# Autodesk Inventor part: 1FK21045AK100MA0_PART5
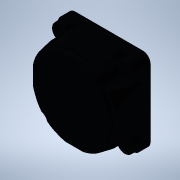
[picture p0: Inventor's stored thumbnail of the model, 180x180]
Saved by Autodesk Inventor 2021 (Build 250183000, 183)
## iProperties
Created: 2025-04
Part Number: 1FK21045AK100MA0_PART5
Material: Generic
Catalog Web Link: www.3dfindit.com
Description: -Servo synchronous motor
Document SubType Name: Modeling
Designer: psAdmin
Mass: 3.92604 g
Surface Area: 17.9521 cm^2
Volume: 3.92604 cm^3
Density: 1 g/cm^3
Appearance: PSOLRGB-48-56-69
Category: PARTsolutions
Title: 1FK21045AK100MA0_PART5
Author: Cadenas PARTsolutions
Comments: Servo synchronous motor
Sending System: PARTsolutions
Preprocessor: ST-DEVELOPER v19.3
PSOL_IDENT_0: {$CADENAS_DATA/23d-libs/siemens_ag/_cat_/e0/5f/1fk21045ak100ma0.prj},213 {VTYP=3D},{NB=1FK21045AK100
PSOL_IDENT_1: MA0_PART5},{LINA=1FK21045AK100MA0_PART5},{NN=1FK21045AK100MA0_PART5},{NOPRJ=TRUE},{DATE=19.08.2025 1
PSOL_IDENT_2: 4:01:03},{GEOMDATE=30.07.2025 02:01:57},{VERSION=},{LINEID=10},{WBVAR=},{WBNUMERIC=}  {NB=1FK21045AK
PSOL_IDENT_3: 100MA0_PART5},{LINA=1FK21045AK100MA0_PART5},{KT=DUMMY},{PREVIEW=../../../_pool_/0f/2c/p_d211_xx_0043
PSOL_IDENT_4: 8j.png},{DESCSHORT=SIMOTICS S-1FK2 HD, SINAMICS S210 3AC 400V-480V, 1.7 Nm, 6000 rpm},{DESCLONG=SIMO
PSOL_IDENT_5: TICS S-1FK2 HD servo motor M0=2.4 Nm; PN = 1.07 kW at nN=6000 rpm (380-480 V); PN = 0.75 kW at nN=30
PSOL_IDENT_6: 00 rpm (200-240 V); with holding brake; degree of protection IP64; cylindrical shaft D19x40mm; absol
PSOL_IDENT_7: ute encoder 22-bit + 12-bit multiturn (encoder AM22DQC); with OCC interface; plug size M17, rotatabl
PSOL_IDENT_8: e; SIMOTICS S-1FK2 servomotorfor a wide range of uses in industrial environments. SIMOTICS S‑1FK2 se
PSOL_IDENT_9: rvomotors are compact synchronous motors with a high dynamic performance that set themselves apart a
PSOL_IDENT_10: s a result of their high power density, degree of protection and overload capability. The motors are
PSOL_IDENT_11: available in two variants: as High Dynamic variant (highest dynamic performance as a result of the
PSOL_IDENT_12: low intrinsic moment of inertia for applications demanding a high dynamic performance with low moved
PSOL_IDENT_13: masses) - and as Compact variant (precise and stable closed-loop control for medium up to large mov
PSOL_IDENT_14: ed masses as a result of a medium intrinsic moment of inertia). SIMOTICSS‑1FK2 servomotors fully exp
PSOL_IDENT_15: loit their strengths in a system with the SINAMICSS210 frequency converter and simple connection usi
PSOL_IDENT_16: ng the one cable connection (OCC). Advantages include the short control and positioning times, fast
PSOL_IDENT_17: and precise correction of disturbing quantities as well as stable control with a high dynamic perfor
PSOL_IDENT_18: mance. The servo motors can be configured to address a wide range of requirements. For example with
PSOL_IDENT_19: and without holding brake, IP64 or IP65 degree of protection, singleturn or multiturn absolute encod
PSOL_IDENT_20: ers - to name just a few. Further, the servomotors are available in different shaft heights extendin
PSOL_IDENT_21: g from 20 to 100. A shaft sealing ring is available to achieve an IP65 degree of protection and for
PSOL_IDENT_22: subsequent mounting at the motor or as spare part. SIMOTICS - the optimum motor for each and every m
PSOL_IDENT_23: otion control application.},{INTNO=804766807114},{SUPPLIERALTNO=1FK2104-5AK10-0MA0},{MANUID=1FK21045
PSOL_IDENT_24: AK100MA0},{MANUNAME=Siemens},{MANUTYPEDESC=Synchronous motor 1FK2-HD 2,39 Nm},{AAU732=SIMOTICS},{AAO
PSOL_IDENT_25: 057=S-1FK2},{AAU734=SIMOTICS S-1FK2 HD servo motor M0=2.4 Nm; PN = 1.07 kW at nN=6000 rpm (380-480 V
PSOL_IDENT_26: ); PN = 0.75 kW at nN=3000 rpm (200-240 V); with holding brake; degree of protection IP64; cylindric
PSOL_IDENT_27: al shaft D19x40mm; absolute encoder 22-bit + 12-bit multiturn (encoder AM22DQC); with OCC interface;
PSOL_IDENT_28: plug size M17, rotatable;},{AAW338=Synchronous motor 1FK2-HD 2,39 Nm},{AAO742=SIMOTICS},{AAO663=404
PSOL_IDENT_29: 2948691236},{NOCUPEROU=1},{PRICEQUANTITY=1},{QUANTITYMIN=1},{QUANTITYINT=1},{CTN=85015100},{COO=DE},
PSOL_IDENT_30: {AAO676=1FK2104-5AK10-0MA0},{AAO677=Siemens AG},{ORDERUNIT=C62},{CONTENTUNIT=C62}
NB: 1FK21045AK100MA0_PART5
NT: Servo synchronous motor
NBSYN: $MANUID._PART5
LINA: 1FK21045AK100MA0_PART5
CATALOG: SIEMENS
PREVIEW: ../../../_pool_/0f/2c/p_d211_xx_00438j.png
DESCSHORT: SIMOTICS S-1FK2 HD, SINAMICS S210 3AC 400V-480V, 1.7 Nm, 6000 rpm
DESCLONG: SIMOTICS S-1FK2 HD servo motor M0=2.4 Nm; PN = 1.07 kW at nN=6000 rpm (380-480 V); PN = 0.75 kW at nN=3000 rpm (200-240 V); with holding brake; degree of protec
INTNO: 804766807114
SUPPLIERALTNO: 1FK2104-5AK10-0MA0
MANUID: 1FK21045AK100MA0
MANUNAME: Siemens
MANUTYPEDESC: Synchronous motor 1FK2-HD 2,39 Nm
AAU732: SIMOTICS
AAO057: S-1FK2
AAU734: SIMOTICS S-1FK2 HD servo motor M0=2.4 Nm; PN = 1.07 kW at nN=6000 rpm (380-480 V); PN = 0.75 kW at nN=3000 rpm (200-240 V); with holding brake; degree of protec
AAW338: Synchronous motor 1FK2-HD 2,39 Nm
AAO742: SIMOTICS
AAO663: 4042948691236.0
NOCUPEROU: 1
PRICEQUANTITY: 1
QUANTITYMIN: 1
QUANTITYINT: 1
CTN: 85015100
COO: DE
ARTICLENO: 1FK21045AK100MA0_PART5
BOMINFO: 1FK21045AK100MA0_PART5
CREATOR: CADENAS GmbH
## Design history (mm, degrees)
feature "2025_04_17_15_45_15_0075"
body "Solid1"
